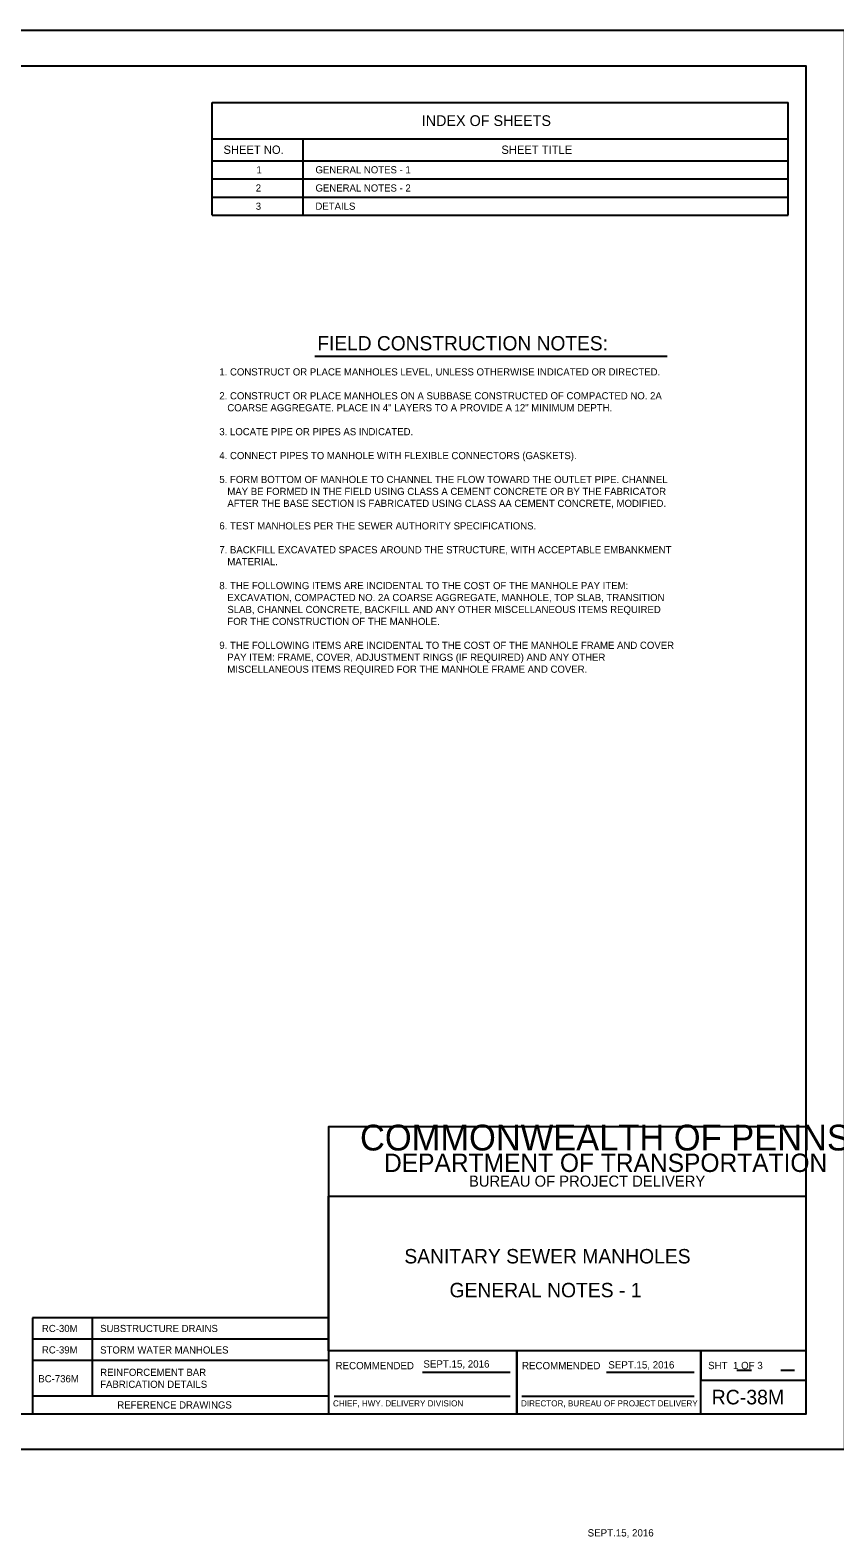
# Model space of a CAD drawing. Extents: x 2106427 to 2114911, y 988717 to 990787.
# Drawn here: x 2108067 to 2109172, y 988717 to 990787 of the extents above; entities that cross this region are included whole.
import ezdxf

# ---------------------------------------------------------------- set-up
doc = ezdxf.new("R2010")
doc.units = 0
for name, color, linetype in [('1', 7, 'Continuous'), ('2', 7, 'Continuous'), ('3', 7, 'Continuous'), ('PLT-BNDY', 7, 'Continuous')]:
    doc.layers.add(name, color=color, linetype=linetype)

msp = doc.modelspace()

# ---------------------------------------------------------------- linework, layer by layer
at = {"layer": '1'}
for p, q in [((2108317.3, 990688.1), (2109108.3, 990688.1)), ((2108317.3, 990533.1), (2108317.3, 990688.1)), ((2109108.3, 990533.1), (2109108.3, 990688.1)), ((2108317.3, 990638.1), (2109108.3, 990638.1)), ((2108442.3, 990533.1), (2108442.3, 990638.1)), ((2108317.3, 990608.1), (2109108.3, 990608.1)), ((2108317.3, 990583.1), (2109108.3, 990583.1)), ((2108317.3, 990558.1), (2109108.3, 990558.1)), ((2108317.3, 990533.1), (2109108.3, 990533.1)), ((2108458.1, 990339.9), (2108942.1, 990339.9)), ((2108070.2, 989019.5), (2108070.2, 988887.7)), ((2108477, 989019.5), (2108070.2, 989019.5)), ((2108152.2, 989019.5), (2108152.2, 988990)), ((2108477, 988990), (2108070.2, 988990)), ((2108152.2, 988990), (2108152.2, 988960.6)), ((2108477, 988960.6), (2108070.2, 988960.6)), ((2108477, 988960.6), (2108070.2, 988960.6)), ((2108152.2, 988970.6), (2108152.2, 988911.7)), ((2108606, 988944.7), (2108726.4, 988944.7)), ((2108858.6, 988944.7), (2108979, 988944.7)), ((2109037.7, 988947.4), (2109057.9, 988947.4)), ((2109098.1, 988947.4), (2109116.9, 988947.4)), ((2108477, 988911.7), (2108070.2, 988911.7)), ((2108484.9, 988911.7), (2108726.4, 988911.7)), ((2108742.6, 988911.7), (2108979, 988911.7))]:
    msp.add_line(p, q, dxfattribs=at)
msp.add_lwpolyline([(2109133.2, 988887.7), (2109133.2, 990738.1), (2106554.5, 990738.1), (2106554.5, 988887.7), (2109133.2, 988887.7), (2109133.2, 988974.2), (2108477, 988974.2), (2108477, 989186.4), (2109133.2, 989186.4), (2109133.2, 989281.4), (2108477, 989281.4), (2108477, 988887.7), (2108735.6, 988887.7), (2108735.6, 988974.2), (2108735.6, 988887.7), (2108988.2, 988887.7), (2108988.2, 988974.2), (2108988.2, 988933.8), (2109133.2, 988933.8)], dxfattribs=at)
at = {"layer": 'PLT-BNDY'}
msp.add_lwpolyline([(2106426.5, 990787.3), (2109185.7, 990787.3), (2109185.7, 988838.5), (2106426.5, 988838.5)], close=True, dxfattribs=at)

# ---------------------------------------------------------------- texts
at = {"layer": '1'}
msp.add_text('SANITARY SEWER MANHOLES', height=19.816, dxfattribs=at).set_placement((2108581.1, 989094))
at = {"layer": '2'}
msp.add_text('GENERAL NOTES - 1', height=19.816, dxfattribs=at).set_placement((2108643.2, 989047.5))
at = {"layer": '3'}
for s, height, p in [('INDEX OF SHEETS', 14.764, (2108604.9, 990655.7)), ('SHEET NO.', 11.48, (2108332.7, 990617.4)), ('SHEET TITLE', 11.483, (2108714.4, 990617.4)), ('1', 9.84, (2108378.1, 990590.7)), ('GENERAL NOTES - 1', 9.843, (2108459, 990590.7)), ('2', 9.84, (2108377, 990565.7)), ('GENERAL NOTES - 2', 9.843, (2108459, 990565.7)), ('3', 9.84, (2108377, 990540.7)), ('DETAILS', 9.84, (2108459, 990540.7)), ('FIELD CONSTRUCTION NOTES:', 19.685, (2108461.5, 990347.6)), ('1. CONSTRUCT OR PLACE MANHOLES LEVEL, UNLESS OTHERWISE INDICATED OR DIRECTED.', 9.843, (2108327, 990313.2)), ('2. CONSTRUCT OR PLACE MANHOLES ON A SUBBASE CONSTRUCTED OF COMPACTED NO. 2A', 9.843, (2108327, 990280.4)), ('   COARSE AGGREGATE. PLACE IN 4" LAYERS TO A PROVIDE A 12" MINIMUM DEPTH.', 9.843, (2108327, 990264)), ('3. LOCATE PIPE OR PIPES AS INDICATED.', 9.843, (2108327, 990231.1)), ('4. CONNECT PIPES TO MANHOLE WITH FLEXIBLE CONNECTORS (GASKETS).', 9.843, (2108327, 990198.3)), ('5. FORM BOTTOM OF MANHOLE TO CHANNEL THE FLOW TOWARD THE OUTLET PIPE. CHANNEL ', 9.843, (2108327, 990165.5)), ('   AFTER THE BASE SECTION IS FABRICATED USING CLASS AA CEMENT CONCRETE, MODIFIED.', 9.843, (2108327, 990132.7)), ('   MAY BE FORMED IN THE FIELD USING CLASS A CEMENT CONCRETE OR BY THE FABRICATOR', 9.843, (2108327, 990149.1)), ('6. TEST MANHOLES PER THE SEWER AUTHORITY SPECIFICATIONS.', 9.843, (2108327, 990101.8)), ('7. BACKFILL EXCAVATED SPACES AROUND THE STRUCTURE, WITH ACCEPTABLE EMBANKMENT', 9.843, (2108327, 990069)), ('   MATERIAL.', 9.843, (2108327, 990052.6)), ('8. THE FOLLOWING ITEMS ARE INCIDENTAL TO THE COST OF THE MANHOLE PAY ITEM:', 9.843, (2108327, 990019.8)), ('   SLAB, CHANNEL CONCRETE, BACKFILL AND ANY OTHER MISCELLANEOUS ITEMS REQUIRED', 9.843, (2108327, 989987)), ('   EXCAVATION, COMPACTED NO. 2A COARSE AGGREGATE, MANHOLE, TOP SLAB, TRANSITION', 9.843, (2108327, 990003.4)), ('   FOR THE CONSTRUCTION OF THE MANHOLE.', 9.843, (2108327, 989970.6)), ('9. THE FOLLOWING ITEMS ARE INCIDENTAL TO THE COST OF THE MANHOLE FRAME AND COVER', 9.843, (2108327, 989937.8)), ('   PAY ITEM: FRAME, COVER, ADJUSTMENT RINGS (IF REQUIRED) AND ANY OTHER ', 9.843, (2108327, 989921.4)), ('   MISCELLANEOUS ITEMS REQUIRED FOR THE MANHOLE FRAME AND COVER. ', 9.843, (2108327, 989905)), ('COMMONWEALTH OF PENNSYLVANIA', 35.379, (2108520.2, 989249.1)), ('DEPARTMENT OF TRANSPORTATION', 25.211, (2108553.2, 989219.6)), ('BUREAU OF PROJECT DELIVERY', 15.164, (2108669.9, 989199.4)), ('RC-30M', 9.84, (2108083.3, 988999.8)), ('SUBSTRUCTURE DRAINS', 9.843, (2108163.3, 988999.8)), ('RC-39M', 9.84, (2108083.3, 988970.4)), ('STORM WATER MANHOLES', 9.843, (2108163.3, 988970.3)), ('SEPT.15, 2016', 10, (2108607.3, 988951)), ('SEPT.15, 2016', 10, (2108861.3, 988949.8)), ('SHT  1 OF 3', 10, (2108998.3, 988948.9)), ('BC-736M', 9.84, (2108078.4, 988930.8)), ('REINFORCEMENT BAR', 9.843, (2108163.3, 988939.6)), ('RECOMMENDED', 10, (2108486.6, 988948.7)), ('RECOMMENDED', 10, (2108742.7, 988948.7)), ('FABRICATION DETAILS', 9.843, (2108163.3, 988923.2)), ('RC-38M', 20, (2109003.2, 988900.5)), ('REFERENCE DRAWINGS', 9.843, (2108186.9, 988894.8)), ('CHIEF, HWY. DELIVERY DIVISION', 8.333, (2108483.1, 988897.7)), ('DIRECTOR, BUREAU OF PROJECT DELIVERY', 8.333, (2108741.4, 988897.7)), ('SEPT.15, 2016', 10, (2108832.9, 988719.1))]:
    msp.add_text(s, height=height, dxfattribs=at).set_placement(p)

doc.saveas('drawing.dxf')
